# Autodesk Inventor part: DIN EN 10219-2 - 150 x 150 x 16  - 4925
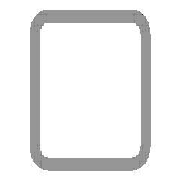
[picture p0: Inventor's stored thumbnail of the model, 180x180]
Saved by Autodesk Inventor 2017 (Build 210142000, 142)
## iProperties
IsCustomPart: 1
Created: 2017-11
Part Number: DIN EN 10219-2 - 150 x 150 x 16  - 4925
Material: Steel, Mild
Description: Cold formed welded structural hollow sections of non-alloy and fine grain structural steel
Document SubType Name: Modeling
Standard: DIN
Designer: iusti
Standard Revision: 2006-07
Standards Organization: DIN
Language: en-US
Size Designation: 150 x 150 x 16
Categories: <MemberInstance><Categories><Category DisplayName="Structural Shapes" InternalName="089c4875-fa83-4c05-b084-43b9cc11f5ed" Mnemonic="GRDR"><CategoryParameter Dis
Stock Number: 150 x 150 x 16
Density: 7.85 g/cm^3
Appearance: Semi-Polished
Mass: 289079 g
Surface Area: 46181.3 cm^2
Volume: 36825.4 cm^3
_CCFamilyMember: 76
_CCFamilyDisplayName: DIN EN 10219-2 (Square Hollow Section - Cold Formed) - Cold formed welded structural hollow sections of non-alloy and fine grain structural steel
_FrameMemberDoc: Frame Member File
_Version: 15.0.0
_GetPNFromCC: 1
G_L: 4925.000 mm
G_W: 150.000 mm
G_H: 150.000 mm
+07E149D3-E7B6-449F-B06C-092C84D7F120+CUTDETAIL1: Cut
Author: iusti
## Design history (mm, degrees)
node "Start plane"
node "End plane"
sketch "Sketch"
  geometry: L1 (-75, -27)-(-75, 27); L2 (-27, 75)-(27, 75); L3 (75, 27)-(75, -27); L4 (27, -75)-(-27, -75); L5 (-27, 59)-(27, 59); L6 (59, 27)-(59, -27); L7 (27, -59)-(-27, -59); L8 (-59, -27)-(-59, 27); L9 (0, 118.918)-(0, -118.918) reference; L10 (-118.918, 0)-(118.918, 0) reference; A1 r 48 centre (-27, -27) between (-75, -27) and (-27, -75); A2 r 48 centre (-27, 27) between (-27, 75) and (-75, 27); A3 r 48 centre (27, 27) between (75, 27) and (27, 75); A4 r 48 centre (27, -27) between (27, -75) and (75, -27); A5 r 32 centre (-27, 27) between (-27, 59) and (-59, 27); A6 r 32 centre (27, 27) between (59, 27) and (27, 59); A7 r 32 centre (27, -27) between (27, -59) and (59, -27); A8 r 32 centre (-27, -27) between (-59, -27) and (-27, -59)
  constraints: 16 end point, 16 point on circle, 8 centre point, 8 tangent, 4 parallel, 3 equal radius, 2 perpendicular, 7 other
  dimensions: "d7" = 48 radius of A1 (= G_IR); "d10" = 150 distance between parallel lines of L2 L4 (= G_H); "d11" = 150 distance between parallel lines of L1 L3 (= G_W); "d12" = 16 distance between parallel lines of L3 L6 (= G_T); "d15" = 75 distance between parallel lines of L2 L10 (= 0.5 x d10); "d16" = 75 distance between parallel lines of L9 L3 (= 0.5 x d11)
extrude "Body" new body sketch "Sketch" stored distance "d3" = 4925 (= G_L); taper "d4" = 0 deg
node "Driven Length"
  sketch "Sketch3"
    geometry: L1 (0, 0)-(10, 0) reference
    constraints: 2 end point, 1 horizontal
  workplane "Work Plane3"
  sketch "Sketch4"
    geometry: L1 (-2, 75)-(12, 75) reference; L2 (-2, 5000)-(12, 5000) reference
    dimensions: "d18" = 4925 distance between parallel lines of L1 L2 (derived)
workplane "Work Plane4"
split "Split1"
body "Solid1"
other parameters: "G_W" = 150 [user parameter; used in 1 equation term], "G_H" = 150 [user parameter; used in 1 equation term], "G_T" = 16 [user parameter; used in 1 equation term], "G_IR" = 48 [user parameter; used in 1 equation term], "G_L" = 4925 (= d18) [user parameter; used in 1 equation term], "G_OFFSET_START" = -75 [user parameter; used in 1 equation term], "G_OFFSET_END" = 0 [user parameter; used in 1 equation term], "d13" = 75 (= -G_OFFSET_START), "d17" = 90 deg
